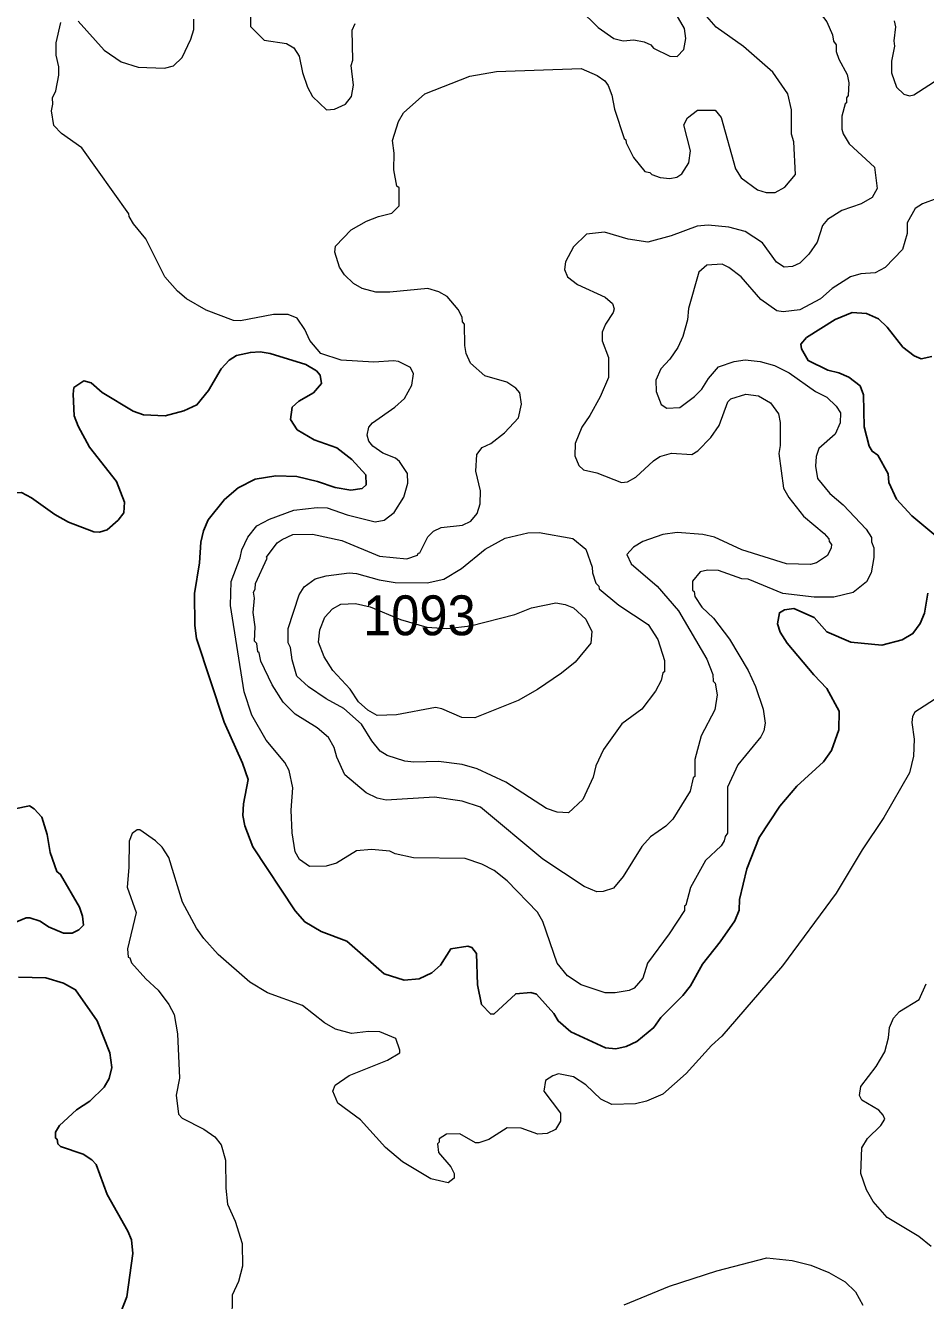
# Model space of a CAD drawing. Extents: x 447.8 to 473.9, y 7733.1 to 7760.8.
# Drawn here: x 462.811 to 464.617, y 7745.588 to 7748.146 of the extents above; entities that cross this region are included whole.
import ezdxf

# ---------------------------------------------------------------- set-up
doc = ezdxf.new("R2010")
doc.units = 0
doc.header["$LTSCALE"] = 0.032
doc.layers.add('1', color=7, linetype='Continuous', lineweight=25)
doc.layers.add('2', color=7, linetype='Continuous', lineweight=13)
doc.layers.add('21', color=7, linetype='Continuous')

msp = doc.modelspace()

# ---------------------------------------------------------------- linework, layer by layer
at = {"layer": '1'}
for points in [[(464.6295, 7747.4823), (464.6081, 7747.4778), (464.594, 7747.4838), (464.5714, 7747.5013), (464.5401, 7747.5411), (464.5227, 7747.558), (464.4988, 7747.5683), (464.47, 7747.5705), (464.4359, 7747.5568), (464.3785, 7747.5206), (464.3672, 7747.5068), (464.3682, 7747.4977), (464.3817, 7747.4741), (464.421, 7747.4548), (464.443, 7747.4495), (464.4635, 7747.4408), (464.4859, 7747.4231), (464.4924, 7747.4055), (464.4943, 7747.3411), (464.5043, 7747.3025), (464.5099, 7747.292), (464.5213, 7747.2842), (464.542, 7747.2468), (464.5438, 7747.2297), (464.5592, 7747.1961), (464.5896, 7747.1625), (464.6375, 7747.1223)], [(464.0717, 7746.1361), (464.0381, 7746.1078), (464.0166, 7746.0976), (463.9958, 7746.0934), (463.9749, 7746.0949), (463.9054, 7746.1273), (463.8802, 7746.1493), (463.8711, 7746.1639), (463.8364, 7746.2026), (463.8254, 7746.2064), (463.7948, 7746.2038), (463.7508, 7746.1629), (463.744, 7746.1632), (463.7261, 7746.1824), (463.7181, 7746.2213), (463.7162, 7746.2843), (463.707, 7746.2967), (463.6986, 7746.2993), (463.6647, 7746.2938), (463.6437, 7746.2611), (463.6266, 7746.2458), (463.601, 7746.2337), (463.5709, 7746.2313), (463.5307, 7746.2436), (463.4559, 7746.3092), (463.4044, 7746.3285), (463.3715, 7746.3478), (463.3521, 7746.3699), (463.2677, 7746.4987), (463.2517, 7746.5403), (463.2476, 7746.5612), (463.2487, 7746.585), (463.2578, 7746.6336), (463.2466, 7746.6661), (463.21, 7746.7488), (463.1544, 7746.9167), (463.1511, 7746.9428), (463.1506, 7747.0065), (463.1602, 7747.0685), (463.1633, 7747.1095), (463.1683, 7747.1326), (463.1776, 7747.1544), (463.2109, 7747.1955), (463.2378, 7747.2185), (463.272, 7747.2363), (463.3137, 7747.2428), (463.3557, 7747.2412), (463.3971, 7747.2317), (463.4325, 7747.2196), (463.4644, 7747.2141), (463.4868, 7747.2172), (463.4951, 7747.2245), (463.4942, 7747.2446), (463.4658, 7747.2755), (463.4359, 7747.2989), (463.3907, 7747.3152), (463.3565, 7747.3352), (463.3432, 7747.3557), (463.3465, 7747.3809), (463.36, 7747.3929), (463.3894, 7747.4096), (463.405, 7747.4284), (463.4024, 7747.4448), (463.3949, 7747.4536), (463.3738, 7747.4659), (463.3025, 7747.4882), (463.2824, 7747.4913), (463.2627, 7747.4906), (463.2345, 7747.4843), (463.2197, 7747.4747), (463.204, 7747.4575), (463.1783, 7747.4141), (463.1553, 7747.3856), (463.1292, 7747.3734), (463.0916, 7747.3631), (463.0483, 7747.3655), (463.0275, 7747.3726), (462.9653, 7747.4099), (462.9434, 7747.4297), (462.9283, 7747.4334), (462.9086, 7747.4199), (462.9069, 7747.407), (462.9092, 7747.3635), (462.9172, 7747.3422), (462.94, 7747.3002), (462.9942, 7747.2316), (463.0101, 7747.1903), (463.0084, 7747.1689), (462.9972, 7747.1536), (462.9751, 7747.1348), (462.9597, 7747.1299), (462.9482, 7747.1302), (462.8977, 7747.15), (462.8704, 7747.1654), (462.8232, 7747.1989)], [(462.8232, 7747.1989), (462.8031, 7747.2091), (462.7629, 7747.2083), (462.7341, 7747.1957), (462.7112, 7747.197), (462.7017, 7747.2063)], [(464.6219, 7747.0073), (464.6151, 7746.9675), (464.6062, 7746.9463), (464.5917, 7746.9263), (464.5701, 7746.914), (464.5292, 7746.903), (464.4671, 7746.9094), (464.4192, 7746.93), (464.3935, 7746.9586), (464.353, 7746.9766), (464.334, 7746.9743), (464.324, 7746.9683), (464.32, 7746.9457), (464.3253, 7746.9295), (464.3398, 7746.9072), (464.3929, 7746.8436), (464.4194, 7746.8164), (464.444, 7746.7709), (464.4434, 7746.733), (464.4284, 7746.6916), (464.4124, 7746.6692), (464.3588, 7746.6203), (464.3246, 7746.5799), (464.2836, 7746.5174), (464.2584, 7746.4545), (464.2441, 7746.3931), (464.243, 7746.3711), (464.2343, 7746.3503), (464.2054, 7746.3082)], [(462.7606, 7746.5688), (462.8191, 7746.5807), (462.8286, 7746.5749), (462.8443, 7746.5582), (462.8547, 7746.5231), (462.8606, 7746.487), (462.8743, 7746.4487), (462.8819, 7746.4431), (462.9195, 7746.3774), (462.926, 7746.3595), (462.9274, 7746.3416), (462.9181, 7746.3318), (462.9048, 7746.3255), (462.8877, 7746.3251), (462.8577, 7746.3383), (462.8411, 7746.3491), (462.8203, 7746.3563), (462.8125, 7746.3563), (462.7306, 7746.3218)], [(464.2054, 7746.3082), (464.1697, 7746.2634), (464.1455, 7746.2193), (464.1302, 7746.2001), (464.0862, 7746.1562), (464.0717, 7746.1361)], [(462.797, 7746.237), (462.8523, 7746.236), (462.8879, 7746.2247), (462.9118, 7746.2117), (462.9551, 7746.1492), (462.9806, 7746.085), (462.9846, 7746.0558), (462.9789, 7746.034)], [(462.9789, 7746.034), (462.9691, 7746.0162), (462.9407, 7745.9879), (462.9134, 7745.971), (462.8797, 7745.9394), (462.8716, 7745.9263)], [(462.8716, 7745.9263), (462.8716, 7745.9142), (462.8747, 7745.9119), (462.876, 7745.9025), (462.8816, 7745.8972), (462.9268, 7745.8822), (462.9445, 7745.8705), (462.953, 7745.8612), (462.9751, 7745.8013), (463.0168, 7745.7275), (463.0238, 7745.7102), (463.0269, 7745.6826), (463.0144, 7745.5956), (462.9894, 7745.5307)]]:
    msp.add_lwpolyline(points, dxfattribs=at)
at = {"layer": '2'}
for points in [[(463.7236, 7747.1869), (463.7244, 7747.2127), (463.7149, 7747.2524), (463.7166, 7747.2858), (463.7275, 7747.2996), (463.7447, 7747.3079), (463.7722, 7747.3291), (463.8006, 7747.3592), (463.8062, 7747.3864), (463.8029, 7747.4095), (463.795, 7747.4184), (463.7768, 7747.431), (463.7332, 7747.4437), (463.7041, 7747.4692), (463.6957, 7747.4881), (463.6925, 7747.5042), (463.6924, 7747.5472), (463.6881, 7747.5516), (463.6872, 7747.5612), (463.6795, 7747.5763), (463.6574, 7747.6026), (463.6405, 7747.6123), (463.6186, 7747.6188), (463.5421, 7747.6115), (463.5141, 7747.6116), (463.4868, 7747.6186), (463.4695, 7747.6289), (463.4513, 7747.6461), (463.4414, 7747.6615), (463.4319, 7747.6914), (463.4336, 7747.7034), (463.4647, 7747.7366), (463.4958, 7747.7537), (463.5193, 7747.763), (463.5466, 7747.7695), (463.5609, 7747.7843), (463.561, 7747.8205), (463.5567, 7747.8243), (463.5506, 7747.8565), (463.5513, 7747.8905), (463.5474, 7747.9156), (463.5597, 7747.9537), (463.57, 7747.971), (463.6128, 7748.0094), (463.7029, 7748.0444), (463.7562, 7748.054), (463.9264, 7748.0604), (463.9583, 7748.0462), (463.9735, 7748.035), (463.9801, 7748.026), (463.9879, 7748.0066), (463.9931, 7747.9784), (464.0122, 7747.9197), (464.0161, 7747.9167), (464.0163, 7747.9109), (464.031, 7747.8813), (464.0538, 7747.8532), (464.0643, 7747.8511), (464.0678, 7747.8473), (464.085, 7747.8412), (464.1041, 7747.8393), (464.1183, 7747.8422), (464.1282, 7747.8487), (464.1425, 7747.8707), (464.1453, 7747.8947), (464.132, 7747.947), (464.1398, 7747.9611), (464.1598, 7747.9764), (464.195, 7747.9765), (464.207, 7747.9618), (464.2356, 7747.8591), (464.2474, 7747.8406), (464.2802, 7747.8167), (464.2974, 7747.8115), (464.3157, 7747.8112), (464.3349, 7747.8221), (464.3561, 7747.8475), (464.3529, 7747.9129), (464.3482, 7747.9285), (464.3481, 7747.9771), (464.3407, 7748.0094), (464.3106, 7748.053), (464.2517, 7748.1039), (464.1969, 7748.1429), (464.1642, 7748.1802)], [(463.9227, 7748.1789), (463.9603, 7748.1425), (463.9919, 7748.12), (464.0108, 7748.1158), (464.0322, 7748.1173), (464.0525, 7748.1135), (464.0659, 7748.1076), (464.071, 7748.1012), (464.1041, 7748.0846), (464.1188, 7748.0843), (464.1325, 7748.098), (464.1363, 7748.1205), (464.1332, 7748.1406), (464.1093, 7748.1821)], [(464.3204, 7748.1928), (464.366, 7748.1879), (464.3913, 7748.1823), (464.406, 7748.1709), (464.4194, 7748.1534), (464.4302, 7748.1275)], [(462.9169, 7748.1551), (462.9691, 7748.0968), (463.003, 7748.0734), (463.0377, 7748.0629), (463.0901, 7748.0605), (463.1082, 7748.0657), (463.1256, 7748.0822), (463.1431, 7748.1192), (463.1488, 7748.1384), (463.149, 7748.1588)], [(463.2628, 7748.163), (463.2628, 7748.1441), (463.2899, 7748.1172), (463.3349, 7748.1102), (463.3496, 7748.1016), (463.3604, 7748.085), (463.367, 7748.0521), (463.3771, 7748.0226), (463.3875, 7748.0038), (463.4153, 7747.9774), (463.4311, 7747.9787), (463.4534, 7747.9885), (463.4656, 7748.0042), (463.4696, 7748.0269), (463.4648, 7748.0659), (463.468, 7748.0766), (463.4667, 7748.137), (463.4727, 7748.1503)], [(464.5541, 7748.1558), (464.5566, 7748.1436), (464.5534, 7748.1153), (464.5548, 7748.105), (464.5485, 7748.0749), (464.5485, 7748.0514), (464.5586, 7748.0227), (464.5734, 7748.0085), (464.585, 7748.0053), (464.5935, 7748.007), (464.6653, 7748.0535)], [(463.5284, 7747.2882), (463.5085, 7747.3025), (463.5001, 7747.3127), (463.4969, 7747.3244), (463.5, 7747.3403), (463.5075, 7747.3495), (463.5524, 7747.3809), (463.5715, 7747.3978), (463.5863, 7747.425), (463.5898, 7747.4478), (463.5839, 7747.4601), (463.5596, 7747.4721), (463.5494, 7747.4737), (463.5103, 7747.4706), (463.445, 7747.4752), (463.4041, 7747.4882), (463.3817, 7747.5141), (463.3717, 7747.5362), (463.3561, 7747.5589), (463.3381, 7747.5667), (463.3089, 7747.5667), (463.2426, 7747.5539), (463.229, 7747.5543), (463.1735, 7747.5755), (463.1343, 7747.5981), (463.116, 7747.6132), (463.0912, 7747.6423), (463.053, 7747.7184), (463.0277, 7747.7481), (463.0191, 7747.7633), (463.0188, 7747.7688), (462.9242, 7747.9011), (462.8839, 7747.9296), (462.8684, 7747.9458), (462.8636, 7747.9752), (462.8665, 7747.9882), (462.8652, 7748.0015), (462.8719, 7748.0151), (462.8781, 7748.0468), (462.878, 7748.0636), (462.8732, 7748.0871), (462.8732, 7748.1117), (462.882, 7748.1523)], [(464.4302, 7748.1275), (464.4324, 7748.1149), (464.4378, 7748.1074), (464.438, 7748.0939), (464.4432, 7748.0788), (464.4601, 7748.0483), (464.4635, 7748.0316), (464.462, 7748.0056), (464.4588, 7748.0014), (464.4587, 7747.9911), (464.456, 7747.9893), (464.4492, 7747.9642), (464.4492, 7747.9383), (464.4517, 7747.9289), (464.4641, 7747.9091), (464.5147, 7747.8624), (464.5204, 7747.8196), (464.5102, 7747.801), (464.4882, 7747.7883), (464.4489, 7747.775), (464.4204, 7747.7574), (464.4105, 7747.7448), (464.3997, 7747.7115), (464.3833, 7747.6879), (464.3647, 7747.6696), (464.35, 7747.6629), (464.3337, 7747.6613), (464.3178, 7747.6716), (464.2899, 7747.7105), (464.2554, 7747.7333), (464.2224, 7747.7415), (464.1808, 7747.7455), (464.159, 7747.7438), (464.1071, 7747.7242), (464.0598, 7747.7118), (464.0207, 7747.7175), (463.9733, 7747.7317), (463.9367, 7747.7279), (463.9108, 7747.7026), (463.8945, 7747.6725), (463.893, 7747.6566), (463.8991, 7747.6423), (463.9187, 7747.6267), (463.9745, 7747.6011), (463.9888, 7747.5883), (463.9921, 7747.5779), (463.9906, 7747.5703), (463.975, 7747.5469), (463.9682, 7747.5314), (463.9682, 7747.5137), (463.9809, 7747.4801), (463.9809, 7747.4401), (463.9641, 7747.4016), (463.9436, 7747.3638), (463.9277, 7747.3408), (463.914, 7747.308), (463.9137, 7747.2832), (463.9218, 7747.2638), (463.9308, 7747.2548), (463.9575, 7747.249), (464.0071, 7747.2292), (464.0189, 7747.2309), (464.0362, 7747.2404), (464.0713, 7747.2731), (464.0841, 7747.2816), (464.1073, 7747.2885), (464.1482, 7747.2854), (464.1603, 7747.2932), (464.1863, 7747.3198), (464.203, 7747.3441), (464.2202, 7747.391), (464.2262, 7747.3972), (464.2564, 7747.407), (464.2823, 7747.4031), (464.3063, 7747.3895), (464.3224, 7747.3675), (464.3257, 7747.3498), (464.3256, 7747.3034), (464.3225, 7747.2874), (464.3321, 7747.2184), (464.3429, 7747.1997), (464.3725, 7747.1622), (464.414, 7747.1272), (464.4232, 7747.1164), (464.4235, 7747.1109), (464.4282, 7747.1054), (464.4281, 7747.0986), (464.4204, 7747.083), (464.3981, 7747.0682), (464.3865, 7747.065), (464.3384, 7747.0666), (464.2483, 7747.0945), (464.1939, 7747.1195), (464.1704, 7747.125), (464.1185, 7747.129)], [(464.6395, 7747.7991), (464.6111, 7747.7887), (464.5966, 7747.779), (464.5806, 7747.7506), (464.5805, 7747.729), (464.571, 7747.6968), (464.5361, 7747.6609), (464.5158, 7747.6499), (464.4872, 7747.6484), (464.4668, 7747.6421), (464.4301, 7747.619), (464.4061, 7747.5981), (464.3651, 7747.5761), (464.3317, 7747.5716), (464.3187, 7747.5736), (464.2866, 7747.5969), (464.2474, 7747.6418), (464.2228, 7747.6608), (464.2093, 7747.6674), (464.1782, 7747.6652), (464.1624, 7747.6517), (464.1414, 7747.5786), (464.1397, 7747.5558), (464.1301, 7747.5221), (464.1204, 7747.5003), (464.1042, 7747.4767), (464.0858, 7747.4573), (464.0759, 7747.4347), (464.077, 7747.4119), (464.0867, 7747.3858), (464.0984, 7747.3783), (464.1239, 7747.3802), (464.1539, 7747.4021), (464.1683, 7747.4166), (464.1814, 7747.4381), (464.2017, 7747.4616), (464.233, 7747.4722), (464.2551, 7747.4753), (464.2855, 7747.4721), (464.3144, 7747.4641), (464.3433, 7747.4496), (464.3965, 7747.4119), (464.4189, 7747.4005)], [(464.4189, 7747.4005), (464.4378, 7747.3823), (464.4462, 7747.3692), (464.4458, 7747.349), (464.4356, 7747.3264), (464.4033, 7747.2977)], [(464.4033, 7747.2977), (464.3979, 7747.2813), (464.3962, 7747.2624), (464.4007, 7747.2378), (464.4253, 7747.2074), (464.4521, 7747.1845), (464.4978, 7747.1357), (464.5084, 7747.119), (464.5085, 7747.1102), (464.5132, 7747.0985), (464.5132, 7747.079), (464.5078, 7747.0479), (464.4984, 7747.0302), (464.4718, 7747.009), (464.4333, 7746.9992), (464.394, 7746.9992), (464.3306, 7747.0068), (464.2615, 7747.0352), (464.2484, 7747.0362), (464.2015, 7747.0529), (464.1797, 7747.0536), (464.165, 7747.0505), (464.1497, 7747.0315), (464.1494, 7747.0132), (464.153, 7747.0111), (464.1542, 7747.0008), (464.1682, 7746.9795), (464.1915, 7746.957), (464.2235, 7746.9152), (464.2614, 7746.852), (464.2758, 7746.8199), (464.2912, 7746.7744), (464.2951, 7746.7465), (464.2927, 7746.7313), (464.2866, 7746.7191), (464.2408, 7746.6628), (464.22, 7746.6179), (464.2198, 7746.5258), (464.215, 7746.5195), (464.2134, 7746.5103), (464.207, 7746.5006), (464.1754, 7746.4711), (464.1457, 7746.4167), (464.1364, 7746.3815), (464.1333, 7746.3793), (464.1335, 7746.3705), (464.1026, 7746.324), (464.0593, 7746.2651), (464.05, 7746.2347), (464.0327, 7746.2149), (464.0226, 7746.2104), (463.9945, 7746.2057), (463.9746, 7746.2057), (463.9262, 7746.2218), (463.899, 7746.2396), (463.8781, 7746.2652), (463.8494, 7746.3486), (463.8384, 7746.3673), (463.7776, 7746.4306), (463.7517, 7746.4509), (463.7266, 7746.4635), (463.6934, 7746.475), (463.5898, 7746.4766), (463.5532, 7746.4845), (463.5423, 7746.4895), (463.5055, 7746.4933), (463.4753, 7746.4907), (463.4352, 7746.4658), (463.4147, 7746.4597), (463.3812, 7746.4593), (463.3609, 7746.473), (463.3527, 7746.4887), (463.3465, 7746.5266), (463.3446, 7746.5721), (463.3476, 7746.6167), (463.3406, 7746.6519), (463.3316, 7746.6674), (463.2943, 7746.7123), (463.2657, 7746.7626), (463.25, 7746.8097), (463.2227, 7746.9825), (463.2243, 7747.031), (463.242, 7747.078), (463.2455, 7747.0947), (463.2573, 7747.1197), (463.2757, 7747.1426), (463.3012, 7747.1562), (463.3496, 7747.174), (463.3968, 7747.1795), (463.4166, 7747.1787), (463.4567, 7747.1647), (463.5132, 7747.1507), (463.531, 7747.1541), (463.5511, 7747.1695), (463.5705, 7747.1999)], [(463.5705, 7747.1999), (463.5784, 7747.2278), (463.5777, 7747.2473), (463.5618, 7747.2715), (463.5535, 7747.2781), (463.5284, 7747.2882)], [(464.0262, 7747.0661), (464.0785, 7747.0218), (464.1214, 7746.9717), (464.178, 7746.8752), (464.1907, 7746.8443), (464.191, 7746.8312), (464.1952, 7746.8266), (464.199, 7746.8033), (464.1946, 7746.7733), (464.1668, 7746.7212), (464.1542, 7746.6737), (464.1541, 7746.6399), (464.1511, 7746.6369), (464.1446, 7746.6099), (464.1102, 7746.5538), (464.0964, 7746.5399), (464.0651, 7746.5184), (464.0478, 7746.4993), (464.0108, 7746.4387), (463.9912, 7746.4158), (463.9703, 7746.409), (463.9577, 7746.4084), (463.9319, 7746.4186), (463.849, 7746.4737), (463.7244, 7746.5779), (463.6873, 7746.5904), (463.6317, 7746.5983), (463.5347, 7746.592), (463.5172, 7746.5959), (463.495, 7746.6066), (463.4521, 7746.6431), (463.4357, 7746.6781), (463.4308, 7746.698), (463.419, 7746.7178), (463.3964, 7746.7372), (463.3525, 7746.7648), (463.3286, 7746.7888), (463.3065, 7746.8235), (463.2837, 7746.8709), (463.2803, 7746.8874), (463.2772, 7746.8896), (463.2756, 7746.9064), (463.2708, 7746.9111), (463.2723, 7746.9398), (463.2684, 7746.9684), (463.2707, 7746.9972), (463.2691, 7747.0093), (463.2723, 7747.0156), (463.2725, 7747.0266), (463.2962, 7747.0774), (463.2952, 7747.0798), (463.3164, 7747.1082), (463.326, 7747.1154), (463.3477, 7747.125), (463.3872, 7747.1259), (463.4462, 7747.1128), (463.5218, 7747.0819), (463.5765, 7747.0766), (463.5975, 7747.0834), (463.5995, 7747.0879), (463.6027, 7747.0885), (463.6185, 7747.1207), (463.6297, 7747.1321), (463.645, 7747.1394), (463.6881, 7747.144), (463.7049, 7747.1516), (463.7178, 7747.1673), (463.7236, 7747.1869)], [(464.1185, 7747.129), (464.0901, 7747.125), (464.0499, 7747.1113), (464.0315, 7747.0995), (464.018, 7747.0849), (464.0262, 7747.0661)], [(464.6444, 7746.8003), (464.5956, 7746.7684), (464.591, 7746.76), (464.5895, 7746.7479), (464.5941, 7746.7145), (464.5933, 7746.6802), (464.5847, 7746.6471), (464.5334, 7746.5574), (464.4901, 7746.4925), (464.4377, 7746.4054), (464.3299, 7746.2595), (464.2084, 7746.1189), (464.1875, 7746.0996), (464.1371, 7746.0436), (464.0902, 7746.0023), (464.0573, 7745.9881), (464.0354, 7745.9827), (463.9875, 7745.9815), (463.9659, 7745.9923), (463.9355, 7746.021)], [(463.8513, 7746.0085), (463.8847, 7745.9644), (463.8847, 7745.9479), (463.8744, 7745.9317), (463.8578, 7745.9235), (463.8394, 7745.9218), (463.8059, 7745.9339), (463.7777, 7745.9347), (463.7408, 7745.9116), (463.7212, 7745.9043), (463.7142, 7745.9047), (463.6827, 7745.9226), (463.6562, 7745.9217), (463.6413, 7745.9129), (463.6411, 7745.9062), (463.638, 7745.9028), (463.6403, 7745.8853), (463.6645, 7745.8566), (463.6715, 7745.843), (463.6715, 7745.834), (463.6592, 7745.8241), (463.6243, 7745.8323), (463.5675, 7745.8662), (463.5337, 7745.8955), (463.4837, 7745.9509), (463.4379, 7745.9842), (463.428, 7746.0086), (463.4327, 7746.0203), (463.4606, 7746.0398), (463.5379, 7746.0706), (463.5621, 7746.085), (463.5625, 7746.0907), (463.5546, 7746.114), (463.5224, 7746.127), (463.4993, 7746.1278), (463.4653, 7746.1239), (463.433, 7746.1325), (463.4112, 7746.1452), (463.3669, 7746.1799), (463.2969, 7746.2053), (463.2614, 7746.2269), (463.1977, 7746.2826), (463.1691, 7746.3146), (463.1545, 7746.3355), (463.1262, 7746.3874), (463.0991, 7746.4768), (463.0853, 7746.4977), (463.0725, 7746.5104), (463.0406, 7746.5323), (463.0351, 7746.5327), (463.0251, 7746.525), (463.0191, 7746.5102), (463.019, 7746.457), (463.0151, 7746.4173), (463.0335, 7746.3667), (463.0159, 7746.2941), (463.0175, 7746.2773), (463.0205, 7746.2759), (463.0241, 7746.2657), (463.053, 7746.2334), (463.0778, 7746.211), (463.0986, 7746.1825), (463.1096, 7746.1623), (463.1161, 7746.1235), (463.12, 7746.0341), (463.1137, 7746.0004), (463.1185, 7745.9622), (463.1259, 7745.9541), (463.1691, 7745.9318), (463.1912, 7745.917), (463.2042, 7745.9008), (463.2123, 7745.8698), (463.2131, 7745.8137), (463.2169, 7745.7814), (463.2322, 7745.7474), (463.2458, 7745.7029), (463.2467, 7745.6574), (463.2385, 7745.6262), (463.226, 7745.5987), (463.2251, 7745.5468)], [(464.6281, 7745.6964), (464.6036, 7745.717), (464.5403, 7745.7547), (464.5121, 7745.7866), (464.4986, 7745.8103), (464.4876, 7745.8433), (464.4891, 7745.8948), (464.501, 7745.9136), (464.5274, 7745.9392), (464.5355, 7745.9518), (464.5324, 7745.9604), (464.5236, 7745.9699), (464.4893, 7745.99), (464.4844, 7745.9999), (464.4873, 7746.0176), (464.5184, 7746.0575), (464.5357, 7746.0872), (464.5427, 7746.1152), (464.5446, 7746.1357), (464.5527, 7746.1548), (464.5646, 7746.1679), (464.6044, 7746.192), (464.6183, 7746.2235)], [(463.9355, 7746.021), (463.9111, 7746.0369), (463.881, 7746.0428), (463.8694, 7746.0391), (463.8548, 7746.0297), (463.8513, 7746.0085)], [(464.0125, 7745.5797), (464.1037, 7745.6172), (464.1985, 7745.6481), (464.2984, 7745.6741), (464.3494, 7745.6686), (464.387, 7745.6591), (464.4231, 7745.6447), (464.4561, 7745.6259), (464.4767, 7745.6058), (464.4914, 7745.579)]]:
    msp.add_lwpolyline(points, dxfattribs=at)
for points in [[(463.9098, 7747.1173), (463.9358, 7747.0955), (463.9486, 7747.0596), (463.9491, 7747.0482), (463.9554, 7747.0275), (463.9616, 7747.0214), (463.9623, 7747.0162), (464.0019, 7746.9834), (464.0603, 7746.9446), (464.0802, 7746.9145), (464.0932, 7746.8725), (464.0932, 7746.8495), (464.09, 7746.8473), (464.0866, 7746.8321), (464.0751, 7746.8106), (464.0476, 7746.7749), (464.008, 7746.7456), (463.971, 7746.6939), (463.9555, 7746.6612), (463.9505, 7746.6385), (463.9296, 7746.5936), (463.9006, 7746.5666), (463.878, 7746.568), (463.8568, 7746.5754), (463.7748, 7746.6284), (463.7175, 7746.655), (463.6873, 7746.6634), (463.6398, 7746.6697), (463.5903, 7746.6682), (463.5723, 7746.6702), (463.5372, 7746.6816), (463.5226, 7746.6906), (463.5063, 7746.7109), (463.4854, 7746.7445), (463.4498, 7746.7761), (463.4148, 7746.7951), (463.3792, 7746.8197), (463.3555, 7746.8411), (463.3462, 7746.8736), (463.3429, 7746.8981), (463.3382, 7746.9079), (463.3382, 7746.9366), (463.3607, 7747.0043), (463.3702, 7747.02), (463.3927, 7747.036), (463.4147, 7747.0424), (463.4606, 7747.048), (463.4756, 7747.0472), (463.5208, 7747.034), (463.5533, 7747.0288), (463.6174, 7747.0281), (463.6504, 7747.0352), (463.6863, 7747.0571), (463.7335, 7747.0958), (463.7738, 7747.1177), (463.8194, 7747.1283), (463.8422, 7747.129)], [(463.8753, 7746.9878), (463.8944, 7746.9847), (463.9109, 7746.9779), (463.9354, 7746.9552), (463.9473, 7746.9307), (463.9455, 7746.9069), (463.9142, 7746.8693), (463.8865, 7746.8467), (463.8386, 7746.8142), (463.7995, 7746.7922), (463.7129, 7746.7571), (463.6867, 7746.7581), (463.6466, 7746.7753), (463.6339, 7746.778), (463.5558, 7746.7635), (463.5169, 7746.7623), (463.4985, 7746.7726), (463.4793, 7746.7897), (463.4625, 7746.8147), (463.4282, 7746.8522), (463.4108, 7746.8795), (463.3992, 7746.9088), (463.4019, 7746.9339), (463.4116, 7746.9594), (463.4276, 7746.9757), (463.4438, 7746.9856), (463.4736, 7746.9864), (463.5032, 7746.9799), (463.5638, 7746.9544), (463.6167, 7746.9391), (463.6569, 7746.9366), (463.7042, 7746.9416), (463.7929, 7746.9644), (463.8267, 7746.9782)]]:
    msp.add_lwpolyline(points, close=True, dxfattribs=at)

# ---------------------------------------------------------------- texts
at = {"layer": '21', "width": 0.95}
msp.add_text('1093', height=0.08, dxfattribs=at).set_placement((463.4886, 7746.923))

doc.saveas('drawing.dxf')
